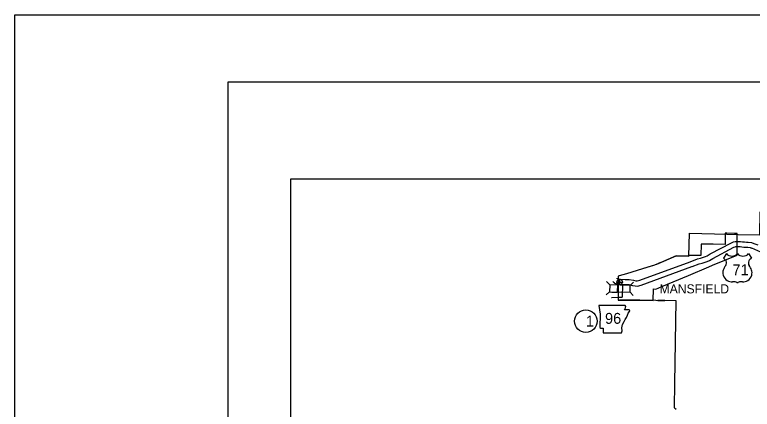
# Model space of a CAD drawing. Extents: x 1382482 to 1385815, y 1168351 to 1170484.
# Drawn here: x 1382481.9 to 1382910.5, y 1170254.7 to 1170484.1 of the extents above; entities that cross this region are included whole.
import ezdxf

# ---------------------------------------------------------------- set-up
doc = ezdxf.new("R2010")
doc.units = 0
for name, color, linetype in [('10', 7, 'Continuous'), ('15', 7, 'Continuous'), ('2', 7, 'Continuous'), ('20', 7, 'Continuous'), ('21', 7, 'Continuous'), ('22', 7, 'Continuous'), ('26', 7, 'Continuous'), ('6', 7, 'Continuous'), ('Default', 7, 'Continuous'), ('R_Border', 7, 'Continuous'), ('R_No Plot', 7, 'Continuous')]:
    doc.layers.add(name, color=color, linetype=linetype)

msp = doc.modelspace()

# ---------------------------------------------------------------- linework, layer by layer
at = {"layer": '10'}
for points in [[(1382832.11, 1170327.37), (1382831.99, 1170322.83)], [(1382835.11, 1170327.25), (1382834.92, 1170319.89)], [(1382828.71, 1170319.76), (1382828.93, 1170319.75), (1382832.73, 1170319.84), (1382832.98, 1170319.86), (1382833.03, 1170319.86), (1382833.19, 1170319.87), (1382833.26, 1170319.88), (1382834.92, 1170319.89)], [(1382828.77, 1170322.76), (1382828.92, 1170322.76), (1382831.99, 1170322.83)], [(1382865.26, 1170255.47), (1382866.24, 1170254.7)]]:
    msp.add_lwpolyline(points, dxfattribs=at)
at = {"layer": '15'}
for points in [[(1382874.37, 1170340.47), (1382878.73, 1170342.16), (1382880.41, 1170342.62), (1382883.23, 1170343.54), (1382884.31, 1170343.98), (1382886.02, 1170344.99), (1382898.45, 1170351.57), (1382899.53, 1170352.09), (1382900.56, 1170352.26), (1382901.64, 1170352.34), (1382902.41, 1170352.32)], [(1382902.49, 1170352.31), (1382903.65, 1170352.27), (1382904.86, 1170352.14), (1382905.89, 1170351.99), (1382907.07, 1170351.92), (1382908.14, 1170351.92), (1382910.04, 1170351.7), (1382911.34, 1170351.17), (1382913.65, 1170350.24)], [(1382875.46, 1170337.67), (1382879.67, 1170339.31), (1382881.27, 1170339.75), (1382884.26, 1170340.72), (1382885.65, 1170341.28), (1382887.48, 1170342.37), (1382899.81, 1170348.89), (1382900.46, 1170349.2), (1382900.92, 1170349.28), (1382901.7, 1170349.34), (1382903.43, 1170349.28), (1382904.48, 1170349.16), (1382905.59, 1170349), (1382906.98, 1170348.92), (1382907.97, 1170348.92), (1382909.29, 1170348.77), (1382910.04, 1170348.46)], [(1382910.05, 1170348.5), (1382915.28, 1170346.21)], [(1382833.61, 1170327.26), (1382836.54, 1170327.19), (1382838.7, 1170327.16), (1382840.85, 1170326.74), (1382842.48, 1170326.46), (1382843.85, 1170326.33), (1382845.93, 1170326.87), (1382875.43, 1170337.66)], [(1382833.68, 1170330.26), (1382836.59, 1170330.19), (1382839.01, 1170330.16), (1382841.4, 1170329.69), (1382842.88, 1170329.43), (1382843.6, 1170329.36), (1382845.03, 1170329.74), (1382874.4, 1170340.48)], [(1382833.46, 1170327.27), (1382832.93, 1170327.33), (1382832.66, 1170327.31), (1382832.37, 1170327.36), (1382832.11, 1170327.39), (1382831.59, 1170327.47), (1382831.4, 1170327.56), (1382831.34, 1170327.57), (1382831.09, 1170327.64), (1382830.6, 1170327.88), (1382830.34, 1170328.13), (1382830.25, 1170328.2), (1382830.15, 1170328.3), (1382830, 1170328.42), (1382829.72, 1170328.73), (1382829.48, 1170329.05)], [(1382833.83, 1170330.25), (1382832.95, 1170330.35), (1382832.8, 1170330.34), (1382832.47, 1170330.37), (1382832.25, 1170330.44), (1382832.23, 1170330.46), (1382832.15, 1170330.54), (1382832.08, 1170330.6), (1382832.04, 1170330.64), (1382831.87, 1170330.86)]]:
    msp.add_lwpolyline(points, dxfattribs=at)
at = {"layer": '2'}
for points in [[(1382902.33, 1170356.42), (1382914.89, 1170356.16), (1382915.11, 1170369.55), (1382935.41, 1170369.13), (1382935.76, 1170375.71), (1382942.25, 1170375.67), (1382942.34, 1170382.04), (1382969.52, 1170381.9), (1382969.61, 1170388.77)], [(1382854.93, 1170339.06), (1382866.2, 1170343.85), (1382873.64, 1170343.75), (1382874.06, 1170357.02), (1382895.73, 1170356.56), (1382902.33, 1170356.42)], [(1382854.93, 1170339.06), (1382853.6, 1170338.48), (1382853.11, 1170338.34), (1382852.32, 1170338.07), (1382851.2, 1170337.75), (1382850.44, 1170337.56), (1382846.68, 1170336.39), (1382837.32, 1170333.49), (1382833.17, 1170332.2)], [(1382833.17, 1170332.2), (1382832.54, 1170332.04), (1382832.54, 1170330.42)], [(1382832.5, 1170319.83), (1382832.5, 1170318.16), (1382833.3, 1170318.16)], [(1382854.45, 1170317.9), (1382845.06, 1170318.14), (1382833.3, 1170318.16)], [(1382865.22, 1170255.61), (1382865.52, 1170269.82), (1382866.2, 1170317.78), (1382854.45, 1170317.9), (1382854.45, 1170318.14)]]:
    msp.add_lwpolyline(points, dxfattribs=at)
at = {"layer": '20'}
for p, q in [((1382827.66, 1170327.01), (1382825.84, 1170328.92)), ((1382839.53, 1170326.71), (1382841.45, 1170328.52)), ((1382827.56, 1170323.05), (1382825.64, 1170321.23)), ((1382839.43, 1170322.75), (1382841.25, 1170320.83))]:
    msp.add_line(p, q, dxfattribs=at)
msp.add_lwpolyline([(1382839.53, 1170326.71), (1382827.66, 1170327.01), (1382827.56, 1170323.05), (1382839.43, 1170322.75)], close=True, dxfattribs=at)
at = {"layer": '21'}
msp.add_lwpolyline([(1382821.38, 1170315.04), (1382822.14, 1170309.97), (1382821.8, 1170302.27), (1382822.48, 1170301.85), (1382823.75, 1170301.85), (1382823.75, 1170299.14), (1382834.41, 1170299.14), (1382834.91, 1170300.24), (1382834.75, 1170302.02), (1382835, 1170304.05), (1382835.93, 1170305.65), (1382836.52, 1170306.84), (1382837.37, 1170308.11), (1382837.88, 1170309.46), (1382838.3, 1170310.56), (1382839.06, 1170311.49), (1382839.23, 1170312.08), (1382838.89, 1170312.51), (1382836.27, 1170312.51), (1382836.86, 1170313.69), (1382836.94, 1170314.45), (1382836.59, 1170315.04)], close=True, dxfattribs=at)
at = {"layer": '22'}
for p, q in [((1382895.41, 1170345.23), (1382893.68, 1170342.55)), ((1382908.28, 1170345.23), (1382910.01, 1170342.55))]:
    msp.add_line(p, q, dxfattribs=at)
for centre, radius, start, end in [((1382898.64, 1170347.94), 4.21, 220.075, 319.6701), ((1382905.06, 1170347.94), 4.21, 220.3299, 319.925), ((1382891.42, 1170338.66), 4.5, 30.7809, 59.9883), ((1382892.41, 1170339.85), 3.08, 328.8105, 21.2108), ((1382911.28, 1170339.85), 3.08, 158.7892, 211.1895), ((1382912.27, 1170338.66), 4.5, 120.0117, 149.2191), ((1382900.47, 1170333.53), 7.19, 138.9565, 162.6913), ((1382903.22, 1170333.53), 7.19, 17.3087, 41.0435), ((1382898.1, 1170334.12), 4.75, 160.9576, 197.3819), ((1382898.87, 1170334.13), 5.5, 195.1074, 237.1312), ((1382904.82, 1170334.13), 5.5, 302.8688, 344.8926), ((1382905.6, 1170334.12), 4.75, 342.6181, 19.0424), ((1382898.97, 1170335.86), 7.06, 244.0771, 269.5779), ((1382899.14, 1170315.87), 12.93, 81.1942, 90.9539), ((1382900.75, 1170327.47), 1.24, 28.0342, 72.9864), ((1382902.94, 1170327.47), 1.24, 107.0136, 151.9658), ((1382904.56, 1170315.87), 12.93, 89.0461, 98.8058), ((1382904.72, 1170335.86), 7.06, 270.4221, 295.9229)]:
    msp.add_arc(centre, radius, start, end, dxfattribs=at)
at = {"layer": '26'}
for p, q in [((1382831.78, 1170328.69), (1382835.03, 1170328.69)), ((1382833.41, 1170327.06), (1382833.41, 1170330.31))]:
    msp.add_line(p, q, dxfattribs=at)
msp.add_circle((1382833.41, 1170328.69), 1.62, dxfattribs=at)
at = {"layer": '6'}
for points in [[(1382852.97, 1170317.94), (1382853.07, 1170324.65), (1382854.46, 1170324.63), (1382858, 1170326.13), (1382864.48, 1170328.8), (1382873.31, 1170332.49), (1382885.3, 1170337.51), (1382887.36, 1170338.4), (1382901.61, 1170344.34), (1382901.68, 1170356.92), (1382900.19, 1170356.94), (1382895.71, 1170357.01), (1382894.76, 1170357.02), (1382894.67, 1170350.52), (1382887.69, 1170350.65), (1382880.71, 1170350.72), (1382880.55, 1170344.15), (1382874.69, 1170344.17)], [(1382873.65, 1170344.18), (1382873.64, 1170343.75), (1382866.2, 1170343.85), (1382858.24, 1170340.46)], [(1382874.69, 1170344.17), (1382873.65, 1170344.18)], [(1382856.05, 1170339.53), (1382854.93, 1170339.06), (1382853.11, 1170338.34), (1382851.2, 1170337.75), (1382846.68, 1170336.39), (1382837.32, 1170333.49), (1382833.17, 1170332.2), (1382832.54, 1170332.04)], [(1382858.24, 1170340.46), (1382857.42, 1170340.1), (1382856.16, 1170339.57), (1382856.05, 1170339.53)], [(1382832.54, 1170331.66), (1382832.54, 1170330.42), (1382832.5, 1170319.83), (1382832.5, 1170318.16), (1382833.3, 1170318.16), (1382845.06, 1170318.14), (1382852.97, 1170317.94)], [(1382832.54, 1170332.04), (1382832.54, 1170331.99), (1382832.54, 1170331.66), (1382832.54, 1170331.66)], [(1382855.59, 1170317.89), (1382859.57, 1170317.85)], [(1382859.57, 1170317.85), (1382859.57, 1170317.89), (1382855.74, 1170317.89), (1382855.59, 1170317.89)]]:
    msp.add_lwpolyline(points, dxfattribs=at)
at = {"layer": 'Default'}
msp.add_circle((1382813.75, 1170305.94), 6.6, dxfattribs=at)
at = {"layer": 'R_Border'}
for p, q in [((1382605.96, 1170445.2), (1385767.76, 1170445.2)), ((1382605.96, 1168390.6), (1382605.96, 1170445.2))]:
    msp.add_line(p, q, dxfattribs=at)
at = {"layer": 'R_No Plot'}
msp.add_line((1382481.95, 1170484.15), (1385815.28, 1170484.15), dxfattribs=at)
for points in [[(1382481.88, 1170484.15), (1385815.28, 1170484.15), (1385815.28, 1168350.77), (1382481.88, 1168350.77)], [(1382642.23, 1170388.77), (1383371.62, 1170388.77), (1383371.62, 1169604.28), (1382642.23, 1169604.28)]]:
    msp.add_lwpolyline(points, close=True, dxfattribs=at)

# ---------------------------------------------------------------- texts
at = {"layer": '21'}
msp.add_text('96', height=6.336, dxfattribs=at).set_placement((1382824.9, 1170304.38))
at = {"layer": '22'}
msp.add_text('71', height=6.336, dxfattribs=at).set_placement((1382898.94, 1170332.65))
at = {"layer": '6'}
msp.add_text('MANSFIELD', height=5.28, dxfattribs=at).set_placement((1382856.58, 1170322.08))
at = {"layer": 'Default'}
msp.add_text('1', height=6.34, dxfattribs=at).set_placement((1382813.75, 1170302.77))

doc.saveas('drawing.dxf')
